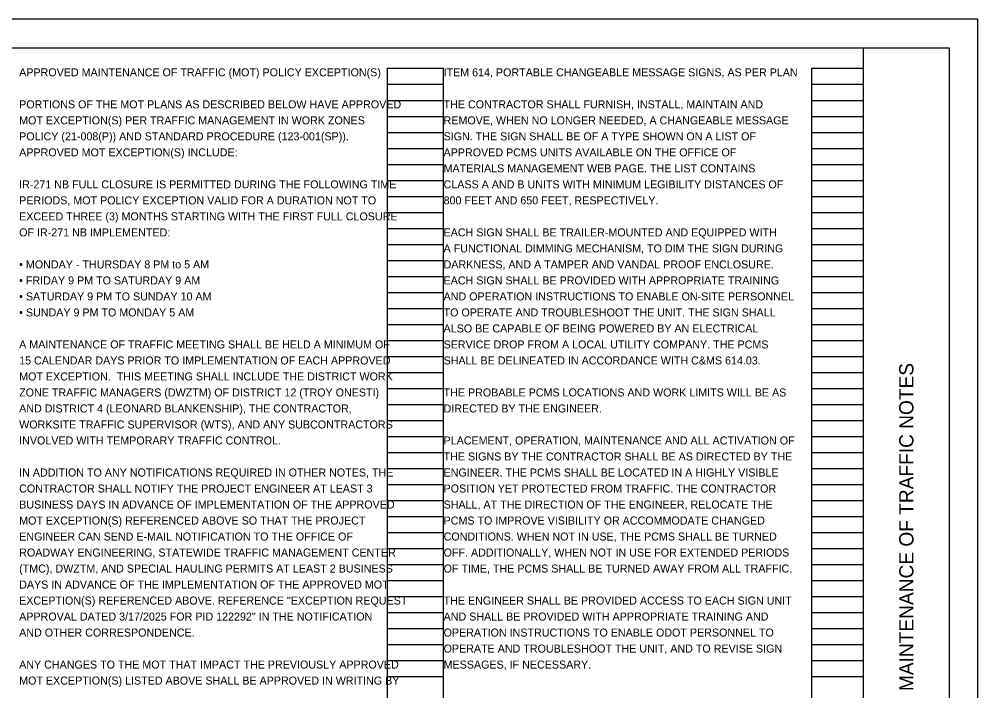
# Model space of a CAD drawing. Extents: x 0 to 49.3, y -31.9 to 22.
# Drawn here: x 17.24 to 34, y 10.25 to 22 of the extents above; entities that cross this region are included whole.
import ezdxf

# ---------------------------------------------------------------- set-up
doc = ezdxf.new("R2010")
doc.units = 0
for name, color, linetype in [('SH_Border', 7, 'Continuous'), ('SH_Cut_Line', 7, 'Continuous'), ('SH_Data', 7, 'Continuous'), ('SH_Text', 7, 'Continuous')]:
    doc.layers.add(name, color=color, linetype=linetype)

msp = doc.modelspace()

# ---------------------------------------------------------------- linework, layer by layer
at = {"layer": 'SH_Border'}
msp.add_line((32, 0.5), (32, 21.5), dxfattribs=at)
msp.add_lwpolyline([(1.5, 21.5), (33.5, 21.5), (33.5, 0.5), (1.5, 0.5)], close=True, dxfattribs=at)
at = {"layer": 'SH_Cut_Line'}
msp.add_lwpolyline([(0, 0), (34, 0), (34, 22), (0, 22)], close=True, dxfattribs=at)
at = {"layer": 'SH_Data'}
for p, q in [((23.68, 0.98), (23.68, 21.14)), ((23.68, 21.14), (24.66, 21.14)), ((24.66, 0.98), (24.66, 21.14)), ((31.1, 0.98), (31.1, 21.14)), ((31.1, 21.14), (32, 21.14)), ((32, 0.98), (32, 21.14)), ((23.68, 20.86), (24.66, 20.86)), ((31.1, 20.86), (32, 20.86)), ((23.68, 20.58), (24.66, 20.58)), ((31.1, 20.58), (32, 20.58)), ((23.68, 20.3), (24.66, 20.3)), ((31.1, 20.3), (32, 20.3)), ((23.68, 20.02), (24.66, 20.02)), ((31.1, 20.02), (32, 20.02)), ((23.68, 19.74), (24.66, 19.74)), ((31.1, 19.74), (32, 19.74)), ((23.68, 19.46), (24.66, 19.46)), ((31.1, 19.46), (32, 19.46)), ((23.68, 19.18), (24.66, 19.18)), ((31.1, 19.18), (32, 19.18)), ((23.68, 18.9), (24.66, 18.9)), ((31.1, 18.9), (32, 18.9)), ((23.68, 18.62), (24.66, 18.62)), ((31.1, 18.62), (32, 18.62)), ((23.68, 18.34), (24.66, 18.34)), ((31.1, 18.34), (32, 18.34)), ((23.68, 18.06), (24.66, 18.06)), ((31.1, 18.06), (32, 18.06)), ((23.68, 17.78), (24.66, 17.78)), ((31.1, 17.78), (32, 17.78)), ((23.68, 17.5), (24.66, 17.5)), ((31.1, 17.5), (32, 17.5)), ((23.68, 17.22), (24.66, 17.22)), ((31.1, 17.22), (32, 17.22)), ((23.68, 16.94), (24.66, 16.94)), ((31.1, 16.94), (32, 16.94)), ((23.68, 16.66), (24.66, 16.66)), ((31.1, 16.66), (32, 16.66)), ((23.68, 16.38), (24.66, 16.38)), ((31.1, 16.38), (32, 16.38)), ((23.68, 16.1), (24.66, 16.1)), ((31.1, 16.1), (32, 16.1)), ((23.68, 15.82), (24.66, 15.82)), ((31.1, 15.82), (32, 15.82)), ((23.68, 15.54), (24.66, 15.54)), ((31.1, 15.54), (32, 15.54)), ((23.68, 15.26), (24.66, 15.26)), ((31.1, 15.26), (32, 15.26)), ((23.68, 14.98), (24.66, 14.98)), ((31.1, 14.98), (32, 14.98)), ((23.68, 14.7), (24.66, 14.7)), ((31.1, 14.7), (32, 14.7)), ((23.68, 14.42), (24.66, 14.42)), ((31.1, 14.42), (32, 14.42)), ((23.68, 14.14), (24.66, 14.14)), ((31.1, 14.14), (32, 14.14)), ((23.68, 13.86), (24.66, 13.86)), ((31.1, 13.86), (32, 13.86)), ((23.68, 13.58), (24.66, 13.58)), ((31.1, 13.58), (32, 13.58)), ((23.68, 13.3), (24.66, 13.3)), ((31.1, 13.3), (32, 13.3)), ((23.68, 13.02), (24.66, 13.02)), ((31.1, 13.02), (32, 13.02)), ((23.68, 12.74), (24.66, 12.74)), ((31.1, 12.74), (32, 12.74)), ((23.68, 12.46), (24.66, 12.46)), ((31.1, 12.46), (32, 12.46)), ((23.68, 12.18), (24.66, 12.18)), ((31.1, 12.18), (32, 12.18)), ((23.68, 11.9), (24.66, 11.9)), ((31.1, 11.9), (32, 11.9)), ((23.68, 11.62), (24.66, 11.62)), ((31.1, 11.62), (32, 11.62)), ((23.68, 11.34), (24.66, 11.34)), ((31.1, 11.34), (32, 11.34)), ((23.68, 11.06), (24.66, 11.06)), ((31.1, 11.06), (32, 11.06)), ((23.68, 10.78), (24.66, 10.78)), ((31.1, 10.78), (32, 10.78)), ((23.68, 10.5), (24.66, 10.5)), ((31.1, 10.5), (32, 10.5))]:
    msp.add_line(p, q, dxfattribs=at)

# ---------------------------------------------------------------- texts
msp.add_text('MAINTENANCE OF TRAFFIC NOTES', height=0.25, rotation=90, dxfattribs=at).set_placement((32.875, 10.247))
at = {"layer": 'SH_Text'}
for s, p in [('APPROVED MAINTENANCE OF TRAFFIC (MOT) POLICY EXCEPTION(S) ', (17.24, 21)), ('ITEM 614, PORTABLE CHANGEABLE MESSAGE SIGNS, AS PER PLAN', (24.66, 21)), ('PORTIONS OF THE MOT PLANS AS DESCRIBED BELOW HAVE APPROVED ', (17.24, 20.44)), ('THE CONTRACTOR SHALL FURNISH, INSTALL, MAINTAIN AND', (24.66, 20.44)), ('MOT EXCEPTION(S) PER TRAFFIC MANAGEMENT IN WORK ZONES ', (17.24, 20.16)), ('REMOVE, WHEN NO LONGER NEEDED, A CHANGEABLE MESSAGE', (24.66, 20.16)), ('POLICY (21-008(P)) AND STANDARD PROCEDURE (123-001(SP)).  ', (17.24, 19.88)), ('SIGN. THE SIGN SHALL BE OF A TYPE SHOWN ON A LIST OF', (24.66, 19.88)), ('APPROVED MOT EXCEPTION(S) INCLUDE:', (17.24, 19.6)), ('APPROVED PCMS UNITS AVAILABLE ON THE OFFICE OF', (24.66, 19.6)), ('MATERIALS MANAGEMENT WEB PAGE. THE LIST CONTAINS', (24.66, 19.32)), ('IR-271 NB FULL CLOSURE IS PERMITTED DURING THE FOLLOWING TIME ', (17.24, 19.04)), ('CLASS A AND B UNITS WITH MINIMUM LEGIBILITY DISTANCES OF', (24.66, 19.04)), ('PERIODS, MOT POLICY EXCEPTION VALID FOR A DURATION NOT TO ', (17.24, 18.76)), ('800 FEET AND 650 FEET, RESPECTIVELY.', (24.66, 18.76)), ('EXCEED THREE (3) MONTHS STARTING WITH THE FIRST FULL CLOSURE ', (17.24, 18.48)), ('OF IR-271 NB IMPLEMENTED:', (17.24, 18.2)), ('EACH SIGN SHALL BE TRAILER-MOUNTED AND EQUIPPED WITH', (24.66, 18.2)), ('A FUNCTIONAL DIMMING MECHANISM, TO DIM THE SIGN DURING', (24.66, 17.92)), ('• MONDAY - THURSDAY 8 PM to 5 AM', (17.24, 17.64)), ('DARKNESS, AND A TAMPER AND VANDAL PROOF ENCLOSURE.', (24.66, 17.64)), ('• FRIDAY 9 PM TO SATURDAY 9 AM', (17.24, 17.36)), ('EACH SIGN SHALL BE PROVIDED WITH APPROPRIATE TRAINING', (24.66, 17.36)), ('• SATURDAY 9 PM TO SUNDAY 10 AM', (17.24, 17.08)), ('AND OPERATION INSTRUCTIONS TO ENABLE ON-SITE PERSONNEL', (24.66, 17.08)), ('• SUNDAY 9 PM TO MONDAY 5 AM', (17.24, 16.8)), ('TO OPERATE AND TROUBLESHOOT THE UNIT. THE SIGN SHALL', (24.66, 16.8)), ('ALSO BE CAPABLE OF BEING POWERED BY AN ELECTRICAL', (24.66, 16.52)), ('A MAINTENANCE OF TRAFFIC MEETING SHALL BE HELD A MINIMUM OF ', (17.24, 16.24)), ('SERVICE DROP FROM A LOCAL UTILITY COMPANY. THE PCMS', (24.66, 16.24)), ('15 CALENDAR DAYS PRIOR TO IMPLEMENTATION OF EACH APPROVED ', (17.24, 15.96)), ('SHALL BE DELINEATED IN ACCORDANCE WITH C&MS 614.03.', (24.66, 15.96)), ('MOT EXCEPTION.  THIS MEETING SHALL INCLUDE THE DISTRICT WORK ', (17.24, 15.68)), ('ZONE TRAFFIC MANAGERS (DWZTM) OF DISTRICT 12 (TROY ONESTI) ', (17.24, 15.4)), ('THE PROBABLE PCMS LOCATIONS AND WORK LIMITS WILL BE AS', (24.66, 15.4)), ('AND DISTRICT 4 (LEONARD BLANKENSHIP), THE CONTRACTOR, ', (17.24, 15.12)), ('DIRECTED BY THE ENGINEER. ', (24.66, 15.12)), ('WORKSITE TRAFFIC SUPERVISOR (WTS), AND ANY SUBCONTRACTORS ', (17.24, 14.84)), ('INVOLVED WITH TEMPORARY TRAFFIC CONTROL.', (17.24, 14.56)), ('PLACEMENT, OPERATION, MAINTENANCE AND ALL ACTIVATION OF', (24.66, 14.56)), ('THE SIGNS BY THE CONTRACTOR SHALL BE AS DIRECTED BY THE', (24.66, 14.28)), ('IN ADDITION TO ANY NOTIFICATIONS REQUIRED IN OTHER NOTES, THE ', (17.24, 14)), ('ENGINEER. THE PCMS SHALL BE LOCATED IN A HIGHLY VISIBLE', (24.66, 14)), ('CONTRACTOR SHALL NOTIFY THE PROJECT ENGINEER AT LEAST 3 ', (17.24, 13.72)), ('POSITION YET PROTECTED FROM TRAFFIC. THE CONTRACTOR', (24.66, 13.72)), ('BUSINESS DAYS IN ADVANCE OF IMPLEMENTATION OF THE APPROVED ', (17.24, 13.44)), ('SHALL, AT THE DIRECTION OF THE ENGINEER, RELOCATE THE', (24.66, 13.44)), ('MOT EXCEPTION(S) REFERENCED ABOVE SO THAT THE PROJECT ', (17.24, 13.16)), ('PCMS TO IMPROVE VISIBILITY OR ACCOMMODATE CHANGED', (24.66, 13.16)), ('ENGINEER CAN SEND E-MAIL NOTIFICATION TO THE OFFICE OF ', (17.24, 12.88)), ('CONDITIONS. WHEN NOT IN USE, THE PCMS SHALL BE TURNED', (24.66, 12.88)), ('ROADWAY ENGINEERING, STATEWIDE TRAFFIC MANAGEMENT CENTER ', (17.24, 12.6)), ('OFF. ADDITIONALLY, WHEN NOT IN USE FOR EXTENDED PERIODS', (24.66, 12.6)), ('(TMC), DWZTM, AND SPECIAL HAULING PERMITS AT LEAST 2 BUSINESS ', (17.24, 12.32)), ('OF TIME, THE PCMS SHALL BE TURNED AWAY FROM ALL TRAFFIC.', (24.66, 12.32)), ('DAYS IN ADVANCE OF THE IMPLEMENTATION OF THE APPROVED MOT ', (17.24, 12.04)), ('EXCEPTION(S) REFERENCED ABOVE. REFERENCE "EXCEPTION REQUEST ', (17.24, 11.76)), ('THE ENGINEER SHALL BE PROVIDED ACCESS TO EACH SIGN UNIT', (24.66, 11.76)), ('APPROVAL DATED 3/17/2025 FOR PID 122292" IN THE NOTIFICATION ', (17.24, 11.48)), ('AND SHALL BE PROVIDED WITH APPROPRIATE TRAINING AND', (24.66, 11.48)), ('AND OTHER CORRESPONDENCE.', (17.24, 11.2)), ('OPERATION INSTRUCTIONS TO ENABLE ODOT PERSONNEL TO', (24.66, 11.2)), ('OPERATE AND TROUBLESHOOT THE UNIT, AND TO REVISE SIGN', (24.66, 10.92)), ('ANY CHANGES TO THE MOT THAT IMPACT THE PREVIOUSLY APPROVED ', (17.24, 10.64)), ('MESSAGES, IF NECESSARY.', (24.66, 10.64)), ('MOT EXCEPTION(S) LISTED ABOVE SHALL BE APPROVED IN WRITING BY ', (17.24, 10.36))]:
    msp.add_text(s, height=0.14, dxfattribs=at).set_placement(p)

doc.saveas('drawing.dxf')
